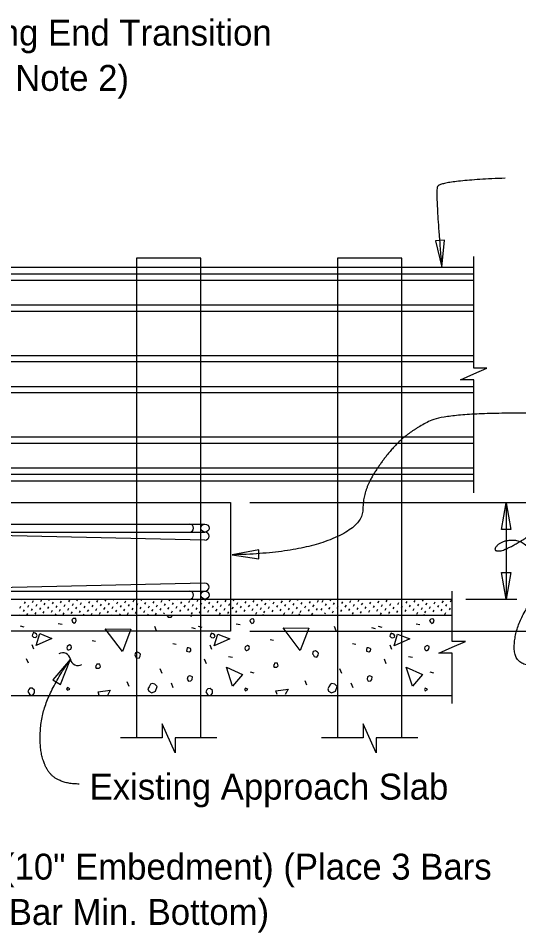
# Model space of a CAD drawing. Extents: x 1.5 to 68.7, y 0 to 31.
# Drawn here: x 32.97 to 36.86, y 9.34 to 16.45 of the extents above; entities that cross this region are included whole.
import ezdxf

# ---------------------------------------------------------------- set-up
doc = ezdxf.new("R2010")
doc.units = 0
for name, color, linetype in [('Dimension', 7, 'Continuous'), ('Miscellaneous', 7, 'Continuous'), ('Rebar', 7, 'Continuous'), ('TextStructures', 7, 'Continuous'), ('TrafBarrierConc', 7, 'Continuous')]:
    doc.layers.add(name, color=color, linetype=linetype)

# ---------------------------------------------------------------- blocks, each defined once
blk = doc.blocks.new('Terminator-Arrow')
at = {"layer": 'Dimension'}
blk.add_lwpolyline([(0, 0), (-0.00041, 0.000069), (-0.00041, -0.000069)], close=True, dxfattribs=at)

msp = doc.modelspace()

# ---------------------------------------------------------------- linework, layer by layer
at = {"layer": 'Dimension'}
for p, q in [((34.7705, 12.682), (37.7448, 12.682)), ((36.763, 12.682), (36.763, 11.932)), ((36.4509, 11.932), (36.8456, 11.932)), ((34.7705, 11.682), (37.7448, 11.682))]:
    msp.add_line(p, q, dxfattribs=at)
for points in [[(36.2627, 14.5121), (36.2835, 14.7223), (36.2131, 14.7174)], [(34.6328, 12.277), (34.8416, 12.2452), (34.8404, 12.3157)], [(33.3771, 11.4646), (33.2393, 11.3045), (33.2997, 11.268)]]:
    msp.add_lwpolyline(points, close=True, dxfattribs=at)
for points in [[(36.5106, 12.7576), (36.5106, 13.6381), (36.4073, 13.6381), (36.5106, 13.6831), (36.6139, 13.7281), (36.5106, 13.7281), (36.5106, 14.5965)], [(36.3442, 11.1206), (36.3442, 11.5124), (36.2408, 11.5124), (36.3442, 11.5574), (36.4475, 11.6024), (36.3442, 11.6024), (36.3442, 11.9928)], [(34.5149, 10.8531), (34.1896, 10.8531), (34.1896, 10.7369), (34.0902, 10.9619), (34.0902, 10.8531), (33.7649, 10.8531)], [(36.0774, 10.8531), (35.7521, 10.8531), (35.7521, 10.7369), (35.6527, 10.9619), (35.6527, 10.8531), (35.3274, 10.8531)]]:
    msp.add_lwpolyline(points, dxfattribs=at)
for centre, start, end in [((33.3177, 11.455), 9.45289, 121.18011), ((33.4353, 11.4746), 189.45289, 301.18011)]:
    msp.add_arc(centre, 0.0596, start, end, dxfattribs=at)
for points in [[(36.7547, 15.2044), (36.2452, 15.1849), (36.212, 15.0904), (36.2626, 14.512)], [(36.9638, 13.3766), (36.3023, 13.3835), (36.0282, 13.2463), (35.8452, 13.0751), (35.6496, 12.7777), (35.6496, 12.4881), (35.1021, 12.2847), (34.6328, 12.2768)], [(36.9767, 11.4144), (36.8259, 11.4144), (36.8259, 11.6957), (37.0041, 11.9975), (37.0041, 12.217), (36.9013, 12.3885), (36.7299, 12.3885), (36.6545, 12.3062), (36.7573, 12.3062), (36.9287, 12.416)], [(33.4454, 10.4942), (33.2528, 10.4942), (33.1238, 10.7493), (33.172, 11.1721), (33.3771, 11.4644)]]:
    msp.add_open_spline(points, degree=2, dxfattribs=at)
at = {"layer": 'Miscellaneous'}
for p, q in [((29.5056, 14.512), (36.5106, 14.512)), ((30.1632, 14.4598), (36.5106, 14.4598)), ((30.1645, 14.4116), (36.5106, 14.4116)), ((30.1692, 14.2188), (36.5106, 14.2188)), ((30.1703, 14.1705), (36.5106, 14.1705)), ((30.1669, 13.8266), (36.5106, 13.8266)), ((30.1656, 13.7783), (36.5106, 13.7783)), ((30.1604, 13.5855), (36.5106, 13.5855)), ((30.1563, 13.5374), (36.5106, 13.5374)), ((30.1703, 13.1934), (36.5106, 13.1934)), ((30.1692, 13.1452), (36.5106, 13.1452)), ((30.1629, 12.9524), (36.5106, 12.9524)), ((30.164, 12.9042), (36.5106, 12.9042)), ((29.5056, 12.8519), (36.5106, 12.8519)), ((32.9832, 11.8622), (32.9913, 11.8762)), ((32.9913, 11.9257), (32.9949, 11.932)), ((33.019, 11.898), (33.0271, 11.912)), ((33.0467, 11.8703), (33.0548, 11.8843)), ((33.0825, 11.9061), (33.0906, 11.9201)), ((33.1101, 11.8784), (33.1182, 11.8924)), ((33.1459, 11.9142), (33.154, 11.9282)), ((33.1736, 11.8865), (33.1817, 11.9005)), ((33.2013, 11.8588), (33.2094, 11.8728)), ((33.2094, 11.9223), (33.215, 11.932)), ((33.2371, 11.8946), (33.2452, 11.9086)), ((33.2648, 11.8669), (33.2729, 11.8809)), ((33.2729, 11.9304), (33.2738, 11.932)), ((33.3006, 11.9027), (33.3087, 11.9167)), ((33.3283, 11.875), (33.3364, 11.889)), ((33.3641, 11.9108), (33.3722, 11.9248)), ((33.3918, 11.8831), (33.3999, 11.8971)), ((33.4276, 11.9189), (33.4352, 11.932)), ((33.4553, 11.8912), (33.4634, 11.9052)), ((33.483, 11.8635), (33.4911, 11.8775)), ((33.4911, 11.927), (33.494, 11.932)), ((33.5188, 11.8993), (33.5269, 11.9133)), ((33.5465, 11.8716), (33.5546, 11.8856)), ((33.5823, 11.9074), (33.5904, 11.9214)), ((33.61, 11.8797), (33.6181, 11.8937)), ((33.6458, 11.9155), (33.6539, 11.9295)), ((33.6735, 11.8878), (33.6816, 11.9018)), ((33.7012, 11.8601), (33.7093, 11.8741)), ((33.7093, 11.9236), (33.7141, 11.932)), ((33.737, 11.8959), (33.7451, 11.9099)), ((33.7647, 11.8682), (33.7728, 11.8822)), ((33.7728, 11.9317), (33.7729, 11.932)), ((33.8005, 11.904), (33.8086, 11.918)), ((33.8282, 11.8763), (33.8363, 11.8903)), ((33.864, 11.9121), (33.8721, 11.9261)), ((33.8916, 11.8844), (33.8997, 11.8984)), ((33.9274, 11.9202), (33.9342, 11.932)), ((33.9551, 11.8925), (33.9632, 11.9065)), ((33.9828, 11.8648), (33.9909, 11.8788)), ((33.9909, 11.9283), (33.993, 11.932)), ((34.0186, 11.9006), (34.0267, 11.9146)), ((34.0463, 11.873), (34.0544, 11.8869)), ((34.0821, 11.9087), (34.0902, 11.9227)), ((34.1072, 11.8818), (34.1153, 11.8958)), ((34.143, 11.9176), (34.1511, 11.9316)), ((34.1707, 11.8899), (34.1788, 11.9039)), ((34.1984, 11.8622), (34.2065, 11.8762)), ((34.2065, 11.9257), (34.2102, 11.932)), ((34.2342, 11.898), (34.2423, 11.912)), ((34.2619, 11.8703), (34.27, 11.8843)), ((34.2977, 11.9061), (34.3058, 11.9201)), ((34.3254, 11.8784), (34.3335, 11.8924)), ((34.3612, 11.9142), (34.3693, 11.9282)), ((34.3889, 11.8865), (34.397, 11.9005)), ((34.4166, 11.8588), (34.4247, 11.8728)), ((34.4247, 11.9223), (34.4303, 11.932)), ((34.4524, 11.8946), (34.4605, 11.9086)), ((34.4801, 11.8669), (34.4882, 11.8809)), ((34.4882, 11.9304), (34.4891, 11.932)), ((34.5159, 11.9027), (34.524, 11.9167)), ((34.5436, 11.875), (34.5517, 11.889)), ((34.5794, 11.9108), (34.5875, 11.9248)), ((34.6071, 11.8831), (34.6152, 11.8971)), ((34.6429, 11.9189), (34.6504, 11.932)), ((34.6706, 11.8912), (34.6787, 11.9052)), ((34.6983, 11.8635), (34.7064, 11.8775)), ((34.7064, 11.927), (34.7092, 11.932)), ((34.7341, 11.8993), (34.7422, 11.9133)), ((34.7618, 11.8716), (34.7699, 11.8856)), ((34.7975, 11.9074), (34.8057, 11.9214)), ((34.8252, 11.8797), (34.8333, 11.8937)), ((34.861, 11.9155), (34.8691, 11.9295)), ((34.8887, 11.8878), (34.8968, 11.9018)), ((34.9164, 11.8601), (34.9245, 11.8741)), ((34.9245, 11.9236), (34.9294, 11.932)), ((34.9522, 11.8959), (34.9603, 11.9099)), ((34.9799, 11.8682), (34.988, 11.8822)), ((34.988, 11.9317), (34.9882, 11.932)), ((35.0157, 11.904), (35.0238, 11.918)), ((35.0434, 11.8763), (35.0515, 11.8903)), ((35.0792, 11.9121), (35.0873, 11.9261)), ((35.1069, 11.8844), (35.115, 11.8984)), ((35.1427, 11.9202), (35.1495, 11.932)), ((35.1704, 11.8925), (35.1785, 11.9065)), ((35.1981, 11.8648), (35.2062, 11.8788)), ((35.2062, 11.9283), (35.2083, 11.932)), ((35.2339, 11.9006), (35.242, 11.9146)), ((35.2616, 11.873), (35.2697, 11.8869)), ((35.2974, 11.9087), (35.3055, 11.9227)), ((35.3331, 11.9087), (35.3412, 11.9227)), ((35.3583, 11.8818), (35.3664, 11.8958)), ((35.3941, 11.9176), (35.4022, 11.9316)), ((35.4217, 11.8899), (35.4298, 11.9039)), ((35.4494, 11.8622), (35.4575, 11.8762)), ((35.4852, 11.898), (35.4933, 11.912)), ((35.5129, 11.8703), (35.521, 11.8843)), ((35.5487, 11.9061), (35.5568, 11.9201)), ((35.5764, 11.8784), (35.5845, 11.8924)), ((35.6122, 11.9142), (35.6203, 11.9282)), ((35.6399, 11.8865), (35.648, 11.9005)), ((35.6676, 11.8588), (35.6757, 11.8728)), ((35.7034, 11.8946), (35.7115, 11.9086)), ((35.7311, 11.8669), (35.7392, 11.8809)), ((35.7669, 11.9027), (35.775, 11.9167)), ((35.7946, 11.875), (35.8027, 11.889)), ((35.8304, 11.9108), (35.8385, 11.9248)), ((35.8581, 11.8831), (35.8662, 11.8971)), ((35.9216, 11.8912), (35.9297, 11.9052)), ((35.9493, 11.8635), (35.9574, 11.8775)), ((35.9851, 11.8993), (35.9932, 11.9133)), ((36.0128, 11.8716), (36.0209, 11.8856)), ((36.0486, 11.9074), (36.0567, 11.9214)), ((36.0763, 11.8797), (36.0844, 11.8937)), ((36.1121, 11.9155), (36.1202, 11.9295)), ((36.1398, 11.8878), (36.1479, 11.9018)), ((36.1675, 11.8601), (36.1756, 11.8741)), ((36.2032, 11.8959), (36.2113, 11.9099)), ((36.2309, 11.8682), (36.239, 11.8822)), ((36.2667, 11.904), (36.2748, 11.918)), ((36.2944, 11.8763), (36.3025, 11.8903)), ((36.3302, 11.9121), (36.3383, 11.9261)), ((32.9798, 11.807), (32.9832, 11.8127)), ((33.0109, 11.8345), (33.019, 11.8485)), ((33.0386, 11.807), (33.0467, 11.8208)), ((33.0743, 11.8426), (33.0825, 11.8566)), ((33.102, 11.8149), (33.1101, 11.8289)), ((33.1378, 11.8507), (33.1459, 11.8647)), ((33.1655, 11.823), (33.1736, 11.837)), ((33.2, 11.807), (33.2013, 11.8093)), ((33.229, 11.8311), (33.2371, 11.8451)), ((33.2588, 11.807), (33.2648, 11.8174)), ((33.2925, 11.8392), (33.3006, 11.8532)), ((33.3202, 11.8115), (33.3283, 11.8255)), ((33.356, 11.8473), (33.3641, 11.8613)), ((33.3837, 11.8196), (33.3918, 11.8336)), ((33.4195, 11.8554), (33.4276, 11.8694)), ((33.4472, 11.8277), (33.4553, 11.8417)), ((33.4789, 11.807), (33.483, 11.814)), ((33.5107, 11.8358), (33.5188, 11.8498)), ((33.5384, 11.8081), (33.5465, 11.8221)), ((33.5742, 11.8439), (33.5823, 11.8579)), ((33.6019, 11.8162), (33.61, 11.8302)), ((33.6377, 11.852), (33.6458, 11.866)), ((33.6654, 11.8243), (33.6735, 11.8383)), ((33.6991, 11.807), (33.7012, 11.8106)), ((33.7289, 11.8324), (33.737, 11.8464)), ((33.7579, 11.807), (33.7647, 11.8187)), ((33.7924, 11.8405), (33.8005, 11.8545)), ((33.8201, 11.8128), (33.8282, 11.8268)), ((33.8558, 11.8486), (33.864, 11.8626)), ((33.8835, 11.8209), (33.8916, 11.8349)), ((33.9192, 11.807), (33.9193, 11.8072)), ((33.9193, 11.8567), (33.9274, 11.8707)), ((33.947, 11.8291), (33.9551, 11.843)), ((33.978, 11.807), (33.9828, 11.8154)), ((34.0105, 11.8372), (34.0186, 11.8511)), ((34.0382, 11.8095), (34.0463, 11.8235)), ((34.074, 11.8453), (34.0821, 11.8593)), ((34.1017, 11.8176), (34.1067, 11.8263)), ((34.1349, 11.8541), (34.143, 11.8681)), ((34.1626, 11.8264), (34.1707, 11.8404)), ((34.2261, 11.8345), (34.2342, 11.8485)), ((34.2896, 11.8426), (34.2977, 11.8566)), ((34.3173, 11.8149), (34.3254, 11.8289)), ((34.3531, 11.8507), (34.3612, 11.8647)), ((34.3808, 11.823), (34.3889, 11.837)), ((34.4443, 11.8311), (34.4524, 11.8451)), ((34.5078, 11.8392), (34.5159, 11.8532)), ((34.5355, 11.8115), (34.5436, 11.8255)), ((34.5713, 11.8473), (34.5794, 11.8613)), ((34.595, 11.807), (34.5964, 11.8093)), ((34.599, 11.8196), (34.6071, 11.8336)), ((34.6348, 11.8554), (34.6429, 11.8694)), ((34.6625, 11.8277), (34.6706, 11.8417)), ((34.726, 11.8358), (34.7341, 11.8498)), ((34.7894, 11.8439), (34.7975, 11.8579)), ((34.8171, 11.8162), (34.8252, 11.8302)), ((34.8529, 11.852), (34.861, 11.866)), ((34.874, 11.807), (34.8781, 11.814)), ((34.8806, 11.8243), (34.8887, 11.8383)), ((34.9441, 11.8324), (34.9522, 11.8464)), ((35.0076, 11.8405), (35.0157, 11.8545)), ((35.0353, 11.8128), (35.0434, 11.8268)), ((35.0711, 11.8486), (35.0792, 11.8626)), ((35.0941, 11.807), (35.0962, 11.8106)), ((35.0988, 11.8209), (35.1069, 11.8349)), ((35.1346, 11.8567), (35.1427, 11.8707)), ((35.1529, 11.807), (35.1597, 11.8187)), ((35.1623, 11.8291), (35.1704, 11.843)), ((35.2258, 11.8372), (35.2339, 11.8511)), ((35.2535, 11.8095), (35.2616, 11.8235)), ((35.2893, 11.8453), (35.2974, 11.8593)), ((35.325, 11.8453), (35.3331, 11.8593)), ((35.3527, 11.8176), (35.3578, 11.8263)), ((35.3859, 11.8541), (35.3941, 11.8681)), ((35.4136, 11.8264), (35.4217, 11.8404)), ((35.4771, 11.8345), (35.4852, 11.8485)), ((35.5406, 11.8426), (35.5487, 11.8566)), ((35.5683, 11.8149), (35.5764, 11.8289)), ((35.6041, 11.8507), (35.6122, 11.8647)), ((35.6318, 11.823), (35.6399, 11.837)), ((35.6953, 11.8311), (35.7034, 11.8451)), ((35.7588, 11.8392), (35.7669, 11.8532)), ((35.7865, 11.8115), (35.7946, 11.8255)), ((35.8223, 11.8473), (35.8304, 11.8613)), ((35.8461, 11.807), (35.8474, 11.8093)), ((35.85, 11.8196), (35.8581, 11.8336)), ((35.8858, 11.8554), (35.8939, 11.8694)), ((35.9135, 11.8277), (35.9216, 11.8417)), ((35.977, 11.8358), (35.9851, 11.8498)), ((36.0405, 11.8439), (36.0486, 11.8579)), ((36.0682, 11.8162), (36.0763, 11.8302)), ((36.104, 11.852), (36.1121, 11.866)), ((36.125, 11.807), (36.1291, 11.814)), ((36.1317, 11.8243), (36.1398, 11.8383)), ((36.1951, 11.8324), (36.2032, 11.8464)), ((36.2586, 11.8405), (36.2667, 11.8545)), ((36.2863, 11.8128), (36.2944, 11.8268)), ((36.3221, 11.8486), (36.3302, 11.8626)), ((33.2826, 11.7433), (33.3126, 11.738)), ((34.6659, 11.7398), (34.6959, 11.7345)), ((36.0629, 11.7398), (36.093, 11.7345)), ((32.9869, 11.7243), (33.0152, 11.7173)), ((34.0445, 11.685), (34.0321, 11.7186)), ((34.3185, 11.7115), (34.3468, 11.7045)), ((34.3702, 11.7208), (34.3985, 11.7137)), ((35.4416, 11.685), (35.4292, 11.7186)), ((35.7156, 11.7115), (35.7439, 11.7045)), ((35.7673, 11.7208), (35.7956, 11.7137)), ((33.546, 11.6108), (33.5725, 11.6055)), ((34.9283, 11.619), (34.9549, 11.6137)), ((33.093, 11.5431), (33.0806, 11.5767)), ((34.1718, 11.586), (34.1983, 11.5807)), ((34.4763, 11.5396), (34.4639, 11.5732)), ((35.5689, 11.586), (35.5954, 11.5807)), ((35.8734, 11.5396), (35.861, 11.5732)), ((33.0506, 11.4335), (33.0364, 11.4689)), ((34.4338, 11.43), (34.4197, 11.4654)), ((34.6058, 11.4852), (34.6376, 11.4817)), ((35.8309, 11.43), (35.8168, 11.4654)), ((36.0028, 11.4852), (36.0347, 11.4817)), ((34.0887, 11.3544), (34.0745, 11.3898)), ((35.4858, 11.3544), (35.4716, 11.3898)), ((34.7737, 11.3668), (34.802, 11.3597)), ((36.1708, 11.3668), (36.1991, 11.3597)), ((33.8324, 11.2537), (33.8182, 11.289)), ((34.1757, 11.2426), (34.1616, 11.278)), ((35.2147, 11.2619), (35.2006, 11.2972)), ((35.5728, 11.2426), (35.5587, 11.278))]:
    msp.add_line(p, q, dxfattribs=at)
for points in [[(34.3899, 10.853), (34.3899, 14.5819), (33.8899, 14.5819), (33.8899, 10.853)], [(35.9524, 10.853), (35.9524, 14.5819), (35.4524, 14.5819), (35.4524, 10.853)], [(34.1266, 11.8069), (34.1364, 11.7911), (34.1594, 11.7928), (34.1682, 11.8017), (34.1735, 11.8069)], [(34.3154, 11.7968), (34.3121, 11.8069)], [(34.3206, 11.8069), (34.3154, 11.7968)], [(33.3939, 11.7557), (33.4046, 11.7451), (33.4152, 11.7522), (33.4222, 11.7628), (33.4187, 11.7805), (33.4099, 11.7822), (33.3975, 11.7805), (33.3869, 11.7699), (33.3939, 11.7557)], [(34.7772, 11.7522), (34.7878, 11.7416), (34.7984, 11.7486), (34.8055, 11.7593), (34.802, 11.7769), (34.7931, 11.7787), (34.7808, 11.7769), (34.7702, 11.7663), (34.7772, 11.7522)], [(36.1743, 11.7522), (36.1849, 11.7416), (36.1955, 11.7486), (36.2026, 11.7593), (36.1991, 11.7769), (36.1902, 11.7787), (36.1778, 11.7769), (36.1672, 11.7663), (36.1743, 11.7522)], [(33.0895, 11.636), (33.1018, 11.6342), (33.1142, 11.6395), (33.1177, 11.6501), (33.1124, 11.6589), (33.1018, 11.666), (33.0895, 11.6713), (33.0824, 11.6572), (33.0788, 11.6466), (33.0895, 11.636)], [(33.1111, 11.5719), (33.1394, 11.6638), (33.2331, 11.6267), (33.1111, 11.5719)], [(33.7811, 11.5241), (33.6467, 11.7009), (33.8465, 11.6991), (33.7811, 11.5241)], [(34.4727, 11.6324), (34.4851, 11.6306), (34.4975, 11.636), (34.501, 11.6466), (34.4957, 11.6554), (34.4851, 11.6625), (34.4727, 11.6678), (34.4657, 11.6536), (34.4621, 11.643), (34.4727, 11.6324)], [(34.4944, 11.5683), (34.5227, 11.6603), (34.6164, 11.6231), (34.4944, 11.5683)], [(35.1634, 11.5323), (35.0291, 11.7091), (35.2289, 11.7074), (35.1634, 11.5323)], [(35.8698, 11.6324), (35.8822, 11.6306), (35.8946, 11.636), (35.8981, 11.6466), (35.8928, 11.6554), (35.8822, 11.6625), (35.8698, 11.6678), (35.8627, 11.6536), (35.8592, 11.643), (35.8698, 11.6324)], [(35.8915, 11.5683), (35.9198, 11.6603), (36.0134, 11.6231), (35.8915, 11.5683)], [(33.3586, 11.5365), (33.3657, 11.5365), (33.3798, 11.5436), (33.3851, 11.5595), (33.3833, 11.5683), (33.3692, 11.5754), (33.3515, 11.5648), (33.348, 11.5542), (33.3515, 11.5436), (33.3586, 11.5365)], [(33.8801, 11.4923), (33.8889, 11.4764), (33.9101, 11.4729), (33.919, 11.4888), (33.9225, 11.5029), (33.9137, 11.5118), (33.8978, 11.5206), (33.8819, 11.5153), (33.8765, 11.4994), (33.8801, 11.4923)], [(34.2796, 11.5277), (34.299, 11.5224), (34.3114, 11.5312), (34.3132, 11.5436), (34.3097, 11.5471), (34.2955, 11.5542), (34.2831, 11.5524), (34.2814, 11.54), (34.2796, 11.5277)], [(34.7419, 11.533), (34.7489, 11.533), (34.7631, 11.54), (34.7684, 11.556), (34.7666, 11.5648), (34.7525, 11.5719), (34.7348, 11.5613), (34.7313, 11.5507), (34.7348, 11.54), (34.7419, 11.533)], [(35.2624, 11.5005), (35.2713, 11.4846), (35.2925, 11.4811), (35.3013, 11.497), (35.3049, 11.5111), (35.296, 11.52), (35.2801, 11.5288), (35.2642, 11.5235), (35.2589, 11.5076), (35.2624, 11.5005)], [(35.6767, 11.5277), (35.6961, 11.5224), (35.7085, 11.5312), (35.7103, 11.5436), (35.7067, 11.5471), (35.6926, 11.5542), (35.6802, 11.5524), (35.6785, 11.54), (35.6767, 11.5277)], [(36.139, 11.533), (36.146, 11.533), (36.1602, 11.54), (36.1655, 11.556), (36.1637, 11.5648), (36.1496, 11.5719), (36.1319, 11.5613), (36.1284, 11.5507), (36.1319, 11.54), (36.139, 11.533)], [(33.5778, 11.3951), (33.599, 11.3951), (33.6096, 11.4057), (33.6043, 11.4251), (33.5813, 11.4269), (33.5778, 11.4163), (33.5725, 11.4075), (33.5778, 11.3951), (33.5743, 11.3986)], [(34.6371, 11.255), (34.5894, 11.4017), (34.7149, 11.3469), (34.6371, 11.255)], [(34.9602, 11.4033), (34.9814, 11.4033), (34.992, 11.4139), (34.9867, 11.4334), (34.9637, 11.4351), (34.9602, 11.4245), (34.9549, 11.4157), (34.9602, 11.4033), (34.9566, 11.4068)], [(36.0342, 11.255), (35.9865, 11.4017), (36.112, 11.3469), (36.0342, 11.255)], [(34.2853, 11.3098), (34.2942, 11.2939), (34.3136, 11.2957), (34.3225, 11.308), (34.3242, 11.3275), (34.3119, 11.3328), (34.303, 11.3345), (34.2924, 11.331), (34.2889, 11.3275), (34.2853, 11.3098)], [(35.6824, 11.3098), (35.6913, 11.2939), (35.7107, 11.2957), (35.7196, 11.308), (35.7213, 11.3275), (35.7089, 11.3328), (35.7001, 11.3345), (35.6895, 11.331), (35.686, 11.3275), (35.6824, 11.3098)], [(33.047, 11.2143), (33.0576, 11.1931), (33.0753, 11.1825), (33.0895, 11.1931), (33.0965, 11.2037), (33.0965, 11.2249), (33.0806, 11.2409), (33.0612, 11.2391), (33.0523, 11.2302), (33.047, 11.2143)], [(33.3528, 11.2232), (33.3723, 11.232), (33.3652, 11.2391), (33.3528, 11.2444), (33.3475, 11.232), (33.3528, 11.2232)], [(33.9862, 11.2165), (34.0091, 11.2042), (34.0392, 11.2165), (34.0516, 11.2537), (34.0339, 11.2713), (34.0109, 11.2767), (34.0003, 11.2696), (33.9879, 11.2501), (33.9791, 11.2342), (33.9862, 11.2165)], [(34.4625, 11.1819), (34.4727, 11.1896), (34.4798, 11.2002), (34.4798, 11.2214), (34.4639, 11.2373), (34.4444, 11.2356), (34.4356, 11.2267), (34.4303, 11.2108)], [(34.7361, 11.2196), (34.7556, 11.2285), (34.7485, 11.2356), (34.7361, 11.2409), (34.7308, 11.2285), (34.7361, 11.2196)], [(35.3832, 11.2165), (35.4062, 11.2042), (35.4363, 11.2165), (35.4486, 11.2537), (35.431, 11.2713), (35.408, 11.2767), (35.3974, 11.2696), (35.385, 11.2501), (35.3762, 11.2342), (35.3832, 11.2165)], [(36.1332, 11.2196), (36.1527, 11.2285), (36.1456, 11.2356), (36.1332, 11.2409), (36.1279, 11.2285), (36.1332, 11.2196)], [(33.6014, 11.1819), (33.5919, 11.2112), (33.6856, 11.2236), (33.6642, 11.1819)], [(34.4303, 11.2108), (34.4409, 11.1896), (34.4537, 11.1819)], [(34.9837, 11.1901), (34.9743, 11.2195), (35.068, 11.2318), (35.0465, 11.1901)]]:
    msp.add_lwpolyline(points, dxfattribs=at)
at = {"layer": 'Rebar'}
for p, q in [((30.7872, 12.5153), (34.4226, 12.5153)), ((30.7872, 12.4528), (34.4226, 12.4528)), ((34.4226, 12.3904), (31.6205, 12.4528)), ((34.4226, 12.0569), (31.6205, 11.9945)), ((30.7872, 11.9945), (34.4226, 11.9945)), ((30.7872, 11.932), (34.4226, 11.932))]:
    msp.add_line(p, q, dxfattribs=at)
for centre in [(34.4226, 12.484), (34.4226, 11.9632)]:
    msp.add_circle(centre, 0.0312, dxfattribs=at)
for centre in [(34.3024, 12.4841), (34.4226, 12.4216), (34.4226, 12.4216), (34.4226, 12.0257), (34.3024, 11.9633)]:
    msp.add_arc(centre, 0.0312, 270, 90, dxfattribs=at)
at = {"layer": 'TrafBarrierConc'}
for p, q in [((25.4726, 12.682), (34.6205, 12.682)), ((31.6205, 12.682), (34.6205, 12.682)), ((34.6205, 12.682), (34.6205, 11.932)), ((34.6205, 12.682), (34.6205, 11.932)), ((31.3067, 11.932), (36.344, 11.932)), ((31.2771, 11.807), (36.344, 11.807)), ((30.6926, 11.182), (36.344, 11.182))]:
    msp.add_line(p, q, dxfattribs=at)
msp.add_lwpolyline([(34.6205, 11.932), (34.6205, 11.682), (31.6205, 11.682), (31.6205, 11.932)], dxfattribs=at)

# ---------------------------------------------------------------- block references
at = {"layer": 'Dimension', "xscale": 506.349, "yscale": -512.1577380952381}
for p, rotation in [((36.7628, 12.6817), 90), ((36.7628, 11.9318), -90)]:
    msp.add_blockref('Terminator-Arrow', p, dxfattribs=dict(at, rotation=rotation))

# ---------------------------------------------------------------- texts
at = {"layer": 'Dimension'}
for s, p in [('Railing End Transition ', (32.3035, 16.2355)), ('(See Note 2)', (32.3035, 15.8835)), ('Dowel Bars 4L (10" Embedment) (Place 3 Bars ', (31.0251, 9.7512)), ('Min. Top and 1 Bar Min. Bottom)', (31.0251, 9.3992))]:
    msp.add_text(s, height=0.2016, dxfattribs=at).set_placement(p)
at = {"layer": 'TextStructures'}
msp.add_text('Existing Approach Slab', height=0.2016, dxfattribs=at).set_placement((33.526, 10.3731))

doc.saveas('drawing.dxf')
